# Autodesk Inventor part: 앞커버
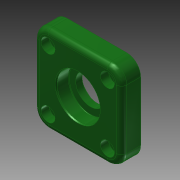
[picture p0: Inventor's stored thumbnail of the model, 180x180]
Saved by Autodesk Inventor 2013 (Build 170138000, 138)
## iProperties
Created: 2018-07
Part Number: 앞커버
Material: 알루미늄 6061
Document SubType Name: Modeling
Designer: mduedu
Density: 1 g/cm^3
Author: mduedu
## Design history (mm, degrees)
sketch "스케치1"
  geometry: C1 r 16 at (0, 0); 1 further point
  constraints: 1 centre point, 1 coincident
  dimensions: "d0" = 32 diameter of C1
extrude "돌출1" new body sketch "스케치1" distance "d1" = 3; taper "d2" = 0 deg
sketch "스케치2"
  geometry: L1 (-25, -25)-(25, -25); L2 (25, -25)-(25, 25); L3 (25, 25)-(-25, 25); L4 (-25, 25)-(-25, -25); L5 (-25, -25)-(25, 25); L6 (25, -25)-(-25, 25); 1 further point
  constraints: 12 end point, 2 midpoint, 2 parallel, 1 horizontal, 1 perpendicular
  dimensions: "d3" = 50 distance of L3.end L2.end; "d4" = 50 distance of L2.end L1.end
extrude "돌출2" join sketch "스케치2" distance "d5" = 11; taper "d6" = 0 deg
hole "구멍1" diameter "d9" = 25; stored, may be unused: countersink angle "d13" = 90 deg, drill point angle "d15" = 0 deg; dims "d7" = 10, "d8" = 10, "d10" = 6, "d11" = 4, "d12" = 2, "d14" = 3
sketch "스케치3"
  geometry: C1 r 12.5 at (0, 0); 1 further point
  constraints: 1 centre point, 1 coincident
  dimensions: "d16" = 25 diameter of C1
extrude "돌출3" cut sketch "스케치3" distance "d17" = 7.3; taper "d18" = 0 deg
sketch "스케치4"
  geometry: C1 r 8.5 at (0, 0); 1 further point
  constraints: 1 centre point, 1 coincident
  dimensions: "d19" = 17 diameter of C1
extrude "돌출4" cut sketch "스케치4" stored distance "d20" = 7.3; taper "d21" = 0 deg
chamfer "모따기1" distance "d22" = 0.7; stored, may be unused: second distance "d23" = 2, angle "d24" = 30 deg
fillet "모깎기1" dims "d25" = 0.3
fillet "모깎기2" dims "d26" = 3
fillet "모깎기3" dims "d27" = 8
sketch "스케치5"
  geometry: L1 (25, -17)-(25, 17) reference; L2 (17, 25)-(-17, 25) reference; L3 (-25, 17)-(-25, -17) reference; L4 (-17, -25)-(17, -25) reference; C1 r 12.904 at (0, 0) reference; A1 r 8 centre (17, -17) between (17, -25) and (25, -17) reference; A2 r 8 centre (17, 17) between (25, 17) and (17, 25) reference; A3 r 8 centre (-17, 17) between (-17, 25) and (-25, 17) reference; A4 r 8 centre (-17, -17) between (-25, -17) and (-17, -25) reference; 5 further points
  constraints: 4 coincident
hole "구멍2" sketch "스케치5" at (-17, 17), (17, 17), (17, -17), (-17, -17) diameter "d28" = 4.5; stored, may be unused: countersink angle "d32" = 90 deg, drill point angle "d34" = 0 deg; dims "d29" = 6, "d30" = 8, "d31" = 4.6, "d33" = 3
fillet "모깎기4" dims "d35" = 3
chamfer "모따기2" distance "d36" = 1; stored, may be unused: second distance "d37" = 2, angle "d38" = 45 deg
node "솔리드1"
node "투영된 루프1"
